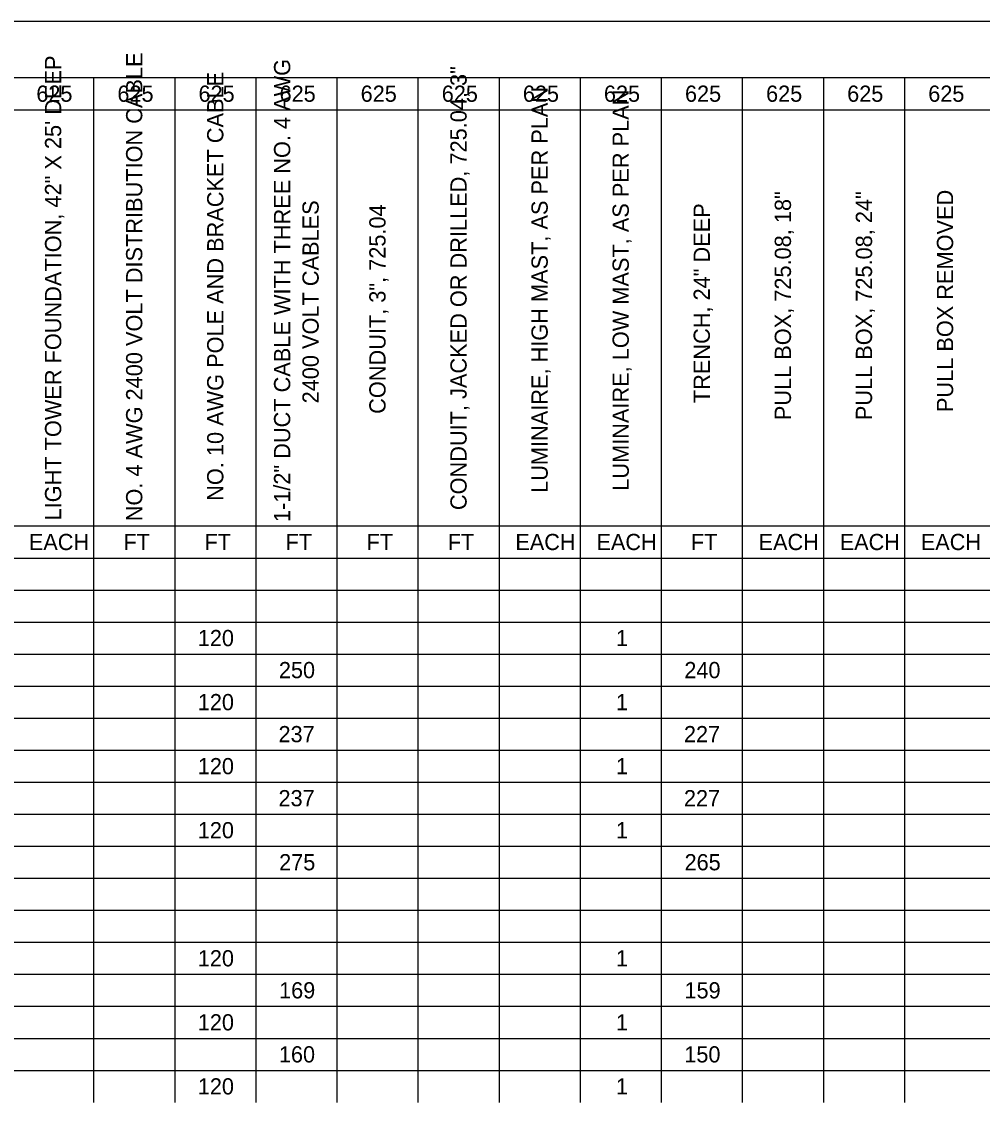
# Model space of a CAD drawing. Extents: x -1022.2 to -988.2, y -965.8 to -943.8.
# Drawn here: x -1005.35 to -996.77, y -953.43 to -943.79 of the extents above; entities that cross this region are included whole.
import ezdxf

# ---------------------------------------------------------------- set-up
doc = ezdxf.new("R2010")
doc.units = 0
for name, color, linetype in [('Default', 7, 'Continuous'), ('SH_Border', 7, 'Continuous'), ('SH_Cut_Line', 7, 'Continuous')]:
    doc.layers.add(name, color=color, linetype=linetype)

msp = doc.modelspace()

# ---------------------------------------------------------------- linework, layer by layer
at = {"layer": 'Default'}
for p, q in [((-1005.4284, -944.2862), (-998.9149, -944.2862)), ((-1004.7047, -944.2862), (-1004.7047, -944.5719)), ((-1003.981, -944.2862), (-1003.981, -944.5719)), ((-1003.2572, -944.2862), (-1003.2572, -944.5719)), ((-1002.5335, -944.2862), (-1002.5335, -944.5719)), ((-1001.8098, -944.2862), (-1001.8098, -944.5719)), ((-1001.0861, -944.2862), (-1001.0861, -944.5719)), ((-1000.3624, -944.2862), (-1000.3624, -944.5719)), ((-999.6387, -944.2862), (-999.6387, -944.5719)), ((-998.9149, -944.2862), (-998.1912, -944.2862)), ((-998.9149, -944.2862), (-998.9149, -944.5719)), ((-998.1912, -944.2862), (-996.0201, -944.2862)), ((-998.1912, -944.2862), (-998.1912, -944.5719)), ((-997.4675, -944.2862), (-997.4675, -944.5719)), ((-1005.4284, -944.5719), (-998.9149, -944.5719)), ((-1004.7047, -944.5719), (-1004.7047, -944.8577)), ((-1003.981, -944.5719), (-1003.981, -944.8577)), ((-1003.2572, -944.5719), (-1003.2572, -944.8577)), ((-1002.5335, -944.5719), (-1002.5335, -944.8577)), ((-1001.8098, -944.5719), (-1001.8098, -944.8577)), ((-1001.0861, -944.5719), (-1001.0861, -944.8577)), ((-1000.3624, -944.5719), (-1000.3624, -944.8577)), ((-999.6387, -944.5719), (-999.6387, -944.8577)), ((-998.9149, -944.5719), (-998.1912, -944.5719)), ((-998.9149, -944.5719), (-998.9149, -944.8577)), ((-998.1912, -944.5719), (-996.0201, -944.5719)), ((-998.1912, -944.5719), (-998.1912, -944.8577)), ((-997.4675, -944.5719), (-997.4675, -944.8577)), ((-1004.7047, -944.8577), (-1004.7047, -945.1434)), ((-1003.981, -944.8577), (-1003.981, -945.1434)), ((-1003.2572, -944.8577), (-1003.2572, -945.1434)), ((-1002.5335, -944.8577), (-1002.5335, -945.1434)), ((-1001.8098, -944.8577), (-1001.8098, -945.1434)), ((-1001.0861, -944.8577), (-1001.0861, -945.1434)), ((-1000.3624, -944.8577), (-1000.3624, -945.1434)), ((-999.6387, -944.8577), (-999.6387, -945.1434)), ((-998.9149, -944.8577), (-998.9149, -945.1434)), ((-998.1912, -944.8577), (-998.1912, -945.1434)), ((-997.4675, -944.8577), (-997.4675, -945.1434)), ((-1004.7047, -945.1434), (-1004.7047, -945.4292)), ((-1003.981, -945.1434), (-1003.981, -945.4292)), ((-1003.2572, -945.1434), (-1003.2572, -945.4292)), ((-1002.5335, -945.1434), (-1002.5335, -945.4292)), ((-1001.8098, -945.1434), (-1001.8098, -945.4292)), ((-1001.0861, -945.1434), (-1001.0861, -945.4292)), ((-1000.3624, -945.1434), (-1000.3624, -945.4292)), ((-999.6387, -945.1434), (-999.6387, -945.4292)), ((-998.9149, -945.1434), (-998.9149, -945.4292)), ((-998.1912, -945.1434), (-998.1912, -945.4292)), ((-997.4675, -945.1434), (-997.4675, -945.4292)), ((-1004.7047, -945.4292), (-1004.7047, -945.7149)), ((-1003.981, -945.4292), (-1003.981, -945.7149)), ((-1003.2572, -945.4292), (-1003.2572, -945.7149)), ((-1002.5335, -945.4292), (-1002.5335, -945.7149)), ((-1001.8098, -945.4292), (-1001.8098, -945.7149)), ((-1001.0861, -945.4292), (-1001.0861, -945.7149)), ((-1000.3624, -945.4292), (-1000.3624, -945.7149)), ((-999.6387, -945.4292), (-999.6387, -945.7149)), ((-998.9149, -945.4292), (-998.9149, -945.7149)), ((-998.1912, -945.4292), (-998.1912, -945.7149)), ((-997.4675, -945.4292), (-997.4675, -945.7149)), ((-1004.7047, -945.7149), (-1004.7047, -946.0006)), ((-1003.981, -945.7149), (-1003.981, -946.0006)), ((-1003.2572, -945.7149), (-1003.2572, -946.0006)), ((-1002.5335, -945.7149), (-1002.5335, -946.0006)), ((-1001.8098, -945.7149), (-1001.8098, -946.0006)), ((-1001.0861, -945.7149), (-1001.0861, -946.0006)), ((-1000.3624, -945.7149), (-1000.3624, -946.0006)), ((-999.6387, -945.7149), (-999.6387, -946.0006)), ((-998.9149, -945.7149), (-998.9149, -946.0006)), ((-998.1912, -945.7149), (-998.1912, -946.0006)), ((-997.4675, -945.7149), (-997.4675, -946.0006)), ((-1004.7047, -946.0006), (-1004.7047, -946.2864)), ((-1003.981, -946.0006), (-1003.981, -946.2864)), ((-1003.2572, -946.0006), (-1003.2572, -946.2864)), ((-1002.5335, -946.0006), (-1002.5335, -946.2864)), ((-1001.8098, -946.0006), (-1001.8098, -946.2864)), ((-1001.0861, -946.0006), (-1001.0861, -946.2864)), ((-1000.3624, -946.0006), (-1000.3624, -946.2864)), ((-999.6387, -946.0006), (-999.6387, -946.2864)), ((-998.9149, -946.0006), (-998.9149, -946.2864)), ((-998.1912, -946.0006), (-998.1912, -946.2864)), ((-997.4675, -946.0006), (-997.4675, -946.2864)), ((-1004.7047, -946.2864), (-1004.7047, -946.8578)), ((-1003.981, -946.2864), (-1003.981, -946.8578)), ((-1003.2572, -946.2864), (-1003.2572, -946.8578)), ((-1002.5335, -946.2864), (-1002.5335, -946.8578)), ((-1001.8098, -946.2864), (-1001.8098, -946.8578)), ((-1001.0861, -946.2864), (-1001.0861, -946.8578)), ((-1000.3624, -946.2864), (-1000.3624, -946.8578)), ((-999.6387, -946.2864), (-999.6387, -946.8578)), ((-998.9149, -946.2864), (-998.9149, -946.8578)), ((-998.1912, -946.2864), (-998.1912, -946.8578)), ((-997.4675, -946.2864), (-997.4675, -946.8578)), ((-1004.7047, -946.8578), (-1004.7047, -947.7151)), ((-1003.981, -946.8578), (-1003.981, -947.7151)), ((-1003.2572, -946.8578), (-1003.2572, -947.7151)), ((-1002.5335, -946.8578), (-1002.5335, -947.7151)), ((-1001.8098, -946.8578), (-1001.8098, -947.7151)), ((-1001.0861, -946.8578), (-1001.0861, -947.7151)), ((-1000.3624, -946.8578), (-1000.3624, -947.7151)), ((-999.6387, -946.8578), (-999.6387, -947.7151)), ((-998.9149, -946.8578), (-998.9149, -947.7151)), ((-998.1912, -946.8578), (-998.1912, -947.7151)), ((-997.4675, -946.8578), (-997.4675, -947.7151)), ((-1004.7047, -947.7151), (-1004.7047, -948.0008)), ((-1003.981, -947.7151), (-1003.981, -948.0008)), ((-1003.2572, -947.7151), (-1003.2572, -948.0008)), ((-1002.5335, -947.7151), (-1002.5335, -948.0008)), ((-1001.8098, -947.7151), (-1001.8098, -948.0008)), ((-1001.0861, -947.7151), (-1001.0861, -948.0008)), ((-1000.3624, -947.7151), (-1000.3624, -948.0008)), ((-999.6387, -947.7151), (-999.6387, -948.0008)), ((-998.9149, -947.7151), (-998.9149, -948.0008)), ((-998.1912, -947.7151), (-998.1912, -948.0008)), ((-997.4675, -947.7151), (-997.4675, -948.0008)), ((-1004.7047, -948.0008), (-1004.7047, -948.5723)), ((-1003.981, -948.0008), (-1003.981, -948.5723)), ((-1003.2572, -948.0008), (-1003.2572, -948.5723)), ((-1002.5335, -948.0008), (-1002.5335, -948.5723)), ((-1001.8098, -948.0008), (-1001.8098, -948.5723)), ((-1001.0861, -948.0008), (-1001.0861, -948.5723)), ((-1000.3624, -948.0008), (-1000.3624, -948.5723)), ((-999.6387, -948.0008), (-999.6387, -948.5723)), ((-998.9149, -948.0008), (-998.9149, -948.5723)), ((-998.1912, -948.0008), (-998.1912, -948.5723)), ((-997.4675, -948.0008), (-997.4675, -948.5723)), ((-1005.4284, -948.2865), (-998.9149, -948.2865)), ((-998.9149, -948.2865), (-998.1912, -948.2865)), ((-998.1912, -948.2865), (-996.0201, -948.2865)), ((-1005.4284, -948.5723), (-998.9149, -948.5723)), ((-1004.7047, -948.5723), (-1004.7047, -948.858)), ((-1003.981, -948.5723), (-1003.981, -948.858)), ((-1003.2572, -948.5723), (-1003.2572, -948.858)), ((-1002.5335, -948.5723), (-1002.5335, -948.858)), ((-1001.8098, -948.5723), (-1001.8098, -948.858)), ((-1001.0861, -948.5723), (-1001.0861, -948.858)), ((-1000.3624, -948.5723), (-1000.3624, -948.858)), ((-999.6387, -948.5723), (-999.6387, -948.858)), ((-998.9149, -948.5723), (-998.1912, -948.5723)), ((-998.9149, -948.5723), (-998.9149, -948.858)), ((-998.1912, -948.5723), (-996.0201, -948.5723)), ((-998.1912, -948.5723), (-998.1912, -948.858)), ((-997.4675, -948.5723), (-997.4675, -948.858)), ((-1005.4284, -948.858), (-998.9149, -948.858)), ((-1004.7047, -948.858), (-1004.7047, -950.001)), ((-1003.981, -948.858), (-1003.981, -950.001)), ((-1003.2572, -948.858), (-1003.2572, -950.001)), ((-1002.5335, -948.858), (-1002.5335, -950.001)), ((-1001.8098, -948.858), (-1001.8098, -950.001)), ((-1001.0861, -948.858), (-1001.0861, -950.001)), ((-1000.3624, -948.858), (-1000.3624, -950.001)), ((-999.6387, -948.858), (-999.6387, -950.001)), ((-998.9149, -948.858), (-998.1912, -948.858)), ((-998.9149, -948.858), (-998.9149, -950.001)), ((-998.1912, -948.858), (-996.0201, -948.858)), ((-998.1912, -948.858), (-998.1912, -950.001)), ((-997.4675, -948.858), (-997.4675, -950.001)), ((-1005.4284, -949.1437), (-998.9149, -949.1437)), ((-998.9149, -949.1437), (-998.1912, -949.1437)), ((-998.1912, -949.1437), (-996.0201, -949.1437)), ((-1005.4284, -949.4295), (-998.9149, -949.4295)), ((-998.9149, -949.4295), (-998.1912, -949.4295)), ((-998.1912, -949.4295), (-996.0201, -949.4295)), ((-1005.4284, -949.7152), (-998.9149, -949.7152)), ((-998.9149, -949.7152), (-998.1912, -949.7152)), ((-998.1912, -949.7152), (-996.0201, -949.7152)), ((-1005.4284, -950.001), (-998.9149, -950.001)), ((-1004.7047, -950.001), (-1004.7047, -950.2867)), ((-1003.981, -950.001), (-1003.981, -950.2867)), ((-1003.2572, -950.001), (-1003.2572, -950.2867)), ((-1002.5335, -950.001), (-1002.5335, -950.2867)), ((-1001.8098, -950.001), (-1001.8098, -950.2867)), ((-1001.0861, -950.001), (-1001.0861, -950.2867)), ((-1000.3624, -950.001), (-1000.3624, -950.2867)), ((-999.6387, -950.001), (-999.6387, -950.2867)), ((-998.9149, -950.001), (-998.1912, -950.001)), ((-998.9149, -950.001), (-998.9149, -950.2867)), ((-998.1912, -950.001), (-996.0201, -950.001)), ((-998.1912, -950.001), (-998.1912, -950.2867)), ((-997.4675, -950.001), (-997.4675, -950.2867)), ((-1005.4284, -950.2867), (-998.9149, -950.2867)), ((-1004.7047, -950.2867), (-1004.7047, -950.8582)), ((-1003.981, -950.2867), (-1003.981, -950.8582)), ((-1003.2572, -950.2867), (-1003.2572, -950.8582)), ((-1002.5335, -950.2867), (-1002.5335, -950.8582)), ((-1001.8098, -950.2867), (-1001.8098, -950.8582)), ((-1001.0861, -950.2867), (-1001.0861, -950.8582)), ((-1000.3624, -950.2867), (-1000.3624, -950.8582)), ((-999.6387, -950.2867), (-999.6387, -950.8582)), ((-998.9149, -950.2867), (-998.1912, -950.2867)), ((-998.9149, -950.2867), (-998.9149, -950.8582)), ((-998.1912, -950.2867), (-996.0201, -950.2867)), ((-998.1912, -950.2867), (-998.1912, -950.8582)), ((-997.4675, -950.2867), (-997.4675, -950.8582)), ((-1005.4284, -950.5724), (-998.9149, -950.5724)), ((-998.9149, -950.5724), (-998.1912, -950.5724)), ((-998.1912, -950.5724), (-996.0201, -950.5724)), ((-1005.4284, -950.8582), (-998.9149, -950.8582)), ((-1004.7047, -950.8582), (-1004.7047, -951.4296)), ((-1003.981, -950.8582), (-1003.981, -951.4296)), ((-1003.2572, -950.8582), (-1003.2572, -951.4296)), ((-1002.5335, -950.8582), (-1002.5335, -951.4296)), ((-1001.8098, -950.8582), (-1001.8098, -951.4296)), ((-1001.0861, -950.8582), (-1001.0861, -951.4296)), ((-1000.3624, -950.8582), (-1000.3624, -951.4296)), ((-999.6387, -950.8582), (-999.6387, -951.4296)), ((-998.9149, -950.8582), (-998.1912, -950.8582)), ((-998.9149, -950.8582), (-998.9149, -951.4296)), ((-998.1912, -950.8582), (-996.0201, -950.8582)), ((-998.1912, -950.8582), (-998.1912, -951.4296)), ((-997.4675, -950.8582), (-997.4675, -951.4296)), ((-1005.4284, -951.1439), (-998.9149, -951.1439)), ((-998.9149, -951.1439), (-998.1912, -951.1439)), ((-998.1912, -951.1439), (-996.0201, -951.1439)), ((-1005.4284, -951.4296), (-998.9149, -951.4296)), ((-1004.7047, -951.4296), (-1004.7047, -951.7154)), ((-1003.981, -951.4296), (-1003.981, -951.7154)), ((-1003.2572, -951.4296), (-1003.2572, -951.7154)), ((-1002.5335, -951.4296), (-1002.5335, -951.7154)), ((-1001.8098, -951.4296), (-1001.8098, -951.7154)), ((-1001.0861, -951.4296), (-1001.0861, -951.7154)), ((-1000.3624, -951.4296), (-1000.3624, -951.7154)), ((-999.6387, -951.4296), (-999.6387, -951.7154)), ((-998.9149, -951.4296), (-998.1912, -951.4296)), ((-998.9149, -951.4296), (-998.9149, -951.7154)), ((-998.1912, -951.4296), (-996.0201, -951.4296)), ((-998.1912, -951.4296), (-998.1912, -951.7154)), ((-997.4675, -951.4296), (-997.4675, -951.7154)), ((-1005.4284, -951.7154), (-998.9149, -951.7154)), ((-1004.7047, -951.7154), (-1004.7047, -952.2869)), ((-1003.981, -951.7154), (-1003.981, -952.2869)), ((-1003.2572, -951.7154), (-1003.2572, -952.2869)), ((-1002.5335, -951.7154), (-1002.5335, -952.2869)), ((-1001.8098, -951.7154), (-1001.8098, -952.2869)), ((-1001.0861, -951.7154), (-1001.0861, -952.2869)), ((-1000.3624, -951.7154), (-1000.3624, -952.2869)), ((-999.6387, -951.7154), (-999.6387, -952.2869)), ((-998.9149, -951.7154), (-998.1912, -951.7154)), ((-998.9149, -951.7154), (-998.9149, -952.2869)), ((-998.1912, -951.7154), (-996.0201, -951.7154)), ((-998.1912, -951.7154), (-998.1912, -952.2869)), ((-997.4675, -951.7154), (-997.4675, -952.2869)), ((-1005.4284, -952.0011), (-998.9149, -952.0011)), ((-998.9149, -952.0011), (-998.1912, -952.0011)), ((-998.1912, -952.0011), (-996.0201, -952.0011)), ((-1005.4284, -952.2869), (-998.9149, -952.2869)), ((-1004.7047, -952.2869), (-1004.7047, -952.5726)), ((-1003.981, -952.2869), (-1003.981, -952.5726)), ((-1003.2572, -952.2869), (-1003.2572, -952.5726)), ((-1002.5335, -952.2869), (-1002.5335, -952.5726)), ((-1001.8098, -952.2869), (-1001.8098, -952.5726)), ((-1001.0861, -952.2869), (-1001.0861, -952.5726)), ((-1000.3624, -952.2869), (-1000.3624, -952.5726)), ((-999.6387, -952.2869), (-999.6387, -952.5726)), ((-998.9149, -952.2869), (-998.1912, -952.2869)), ((-998.9149, -952.2869), (-998.9149, -952.5726)), ((-998.1912, -952.2869), (-996.0201, -952.2869)), ((-998.1912, -952.2869), (-998.1912, -952.5726)), ((-997.4675, -952.2869), (-997.4675, -952.5726)), ((-1005.4284, -952.5726), (-998.9149, -952.5726)), ((-1004.7047, -952.5726), (-1004.7047, -953.4298)), ((-1003.981, -952.5726), (-1003.981, -953.4298)), ((-1003.2572, -952.5726), (-1003.2572, -953.4298)), ((-1002.5335, -952.5726), (-1002.5335, -953.4298)), ((-1001.8098, -952.5726), (-1001.8098, -953.4298)), ((-1001.0861, -952.5726), (-1001.0861, -953.4298)), ((-1000.3624, -952.5726), (-1000.3624, -953.4298)), ((-999.6387, -952.5726), (-999.6387, -953.4298)), ((-998.9149, -952.5726), (-998.1912, -952.5726)), ((-998.9149, -952.5726), (-998.9149, -953.4298)), ((-998.1912, -952.5726), (-996.0201, -952.5726)), ((-998.1912, -952.5726), (-998.1912, -953.4298)), ((-997.4675, -952.5726), (-997.4675, -953.4298)), ((-1005.4284, -952.8583), (-998.9149, -952.8583)), ((-998.9149, -952.8583), (-998.1912, -952.8583)), ((-998.1912, -952.8583), (-996.0201, -952.8583)), ((-1005.4284, -953.1441), (-998.9149, -953.1441)), ((-998.9149, -953.1441), (-998.1912, -953.1441)), ((-998.1912, -953.1441), (-996.0201, -953.1441))]:
    msp.add_line(p, q, dxfattribs=at)
at = {"layer": 'SH_Border'}
msp.add_lwpolyline([(-1020.7494, -944.2862), (-988.7494, -944.2862), (-988.7494, -965.2862), (-1020.7494, -965.2862)], close=True, dxfattribs=at)
at = {"layer": 'SH_Cut_Line'}
msp.add_lwpolyline([(-1022.2494, -965.7862), (-988.2494, -965.7862), (-988.2494, -943.7862), (-1022.2494, -943.7862)], close=True, dxfattribs=at)

# ---------------------------------------------------------------- texts
at = {"layer": 'Default'}
for s, p in [('LIGHT TOWER FOUNDATION, 42" X 25\' DEEP', (-1004.994, -948.2371)), ('NO. 4 AWG 2400 VOLT DISTRIBUTION CABLE', (-1004.2703, -948.2446)), ('1-1/2" DUCT CABLE WITH THREE NO. 4 AWG ', (-1002.9498, -948.2523)), ('CONDUIT, JACKED OR DRILLED, 725.04, 3"', (-1001.3754, -948.1448)), ('NO. 10 AWG POLE AND BRACKET CABLE', (-1003.5466, -948.062)), ('LUMINAIRE, HIGH MAST, AS PER PLAN', (-1000.6517, -947.9914)), ('LUMINAIRE, LOW MAST, AS PER PLAN', (-999.928, -947.972)), ('PULL BOX, 725.08, 18"', (-998.4805, -947.3423)), ('PULL BOX, 725.08, 24"', (-997.7568, -947.3423)), ('PULL BOX REMOVED', (-997.0331, -947.2702)), ('2400 VOLT CABLES', (-1002.6959, -947.1929)), ('CONDUIT, 3", 725.04', (-1002.0991, -947.2861)), ('TRENCH, 24" DEEP', (-999.2043, -947.1904))]:
    msp.add_text(s, height=0.145085, rotation=90, dxfattribs=at).set_placement(p)
for s, height, p in [('625', 0.14457, (-1005.2161, -944.5014)), ('625', 0.14457, (-1004.4924, -944.5014)), ('625', 0.14457, (-1003.7687, -944.5014)), ('625', 0.14457, (-1003.045, -944.5014)), ('625', 0.14457, (-1002.3213, -944.5014)), ('625', 0.14457, (-1001.5975, -944.5014)), ('625', 0.14457, (-1000.8738, -944.5014)), ('625', 0.14457, (-1000.1501, -944.5014)), ('625', 0.14457, (-999.4264, -944.5014)), ('625', 0.14457, (-998.7027, -944.5014)), ('625', 0.14457, (-997.9789, -944.5014)), ('625', 0.14457, (-997.2552, -944.5014)), ('EACH', 0.14457, (-1005.2826, -948.5017)), ('EACH', 0.14457, (-1000.9403, -948.5017)), ('EACH', 0.14457, (-1000.2166, -948.5017)), ('EACH', 0.14457, (-998.7691, -948.5017)), ('EACH', 0.14457, (-998.0454, -948.5017)), ('EACH', 0.14457, (-997.3217, -948.5017)), ('FT', 0.14457, (-1004.4391, -948.5017)), ('FT', 0.14457, (-1003.7154, -948.5017)), ('FT', 0.14457, (-1002.9916, -948.5017)), ('FT', 0.14457, (-1002.2679, -948.5017)), ('FT', 0.14457, (-1001.5442, -948.5017)), ('FT', 0.14457, (-999.373, -948.5017)), ('120', 0.14457, (-1003.7748, -949.3589)), ('1', 0.1446, (-1000.0425, -949.3589)), ('250', 0.14457, (-1003.0511, -949.6446)), ('240', 0.14457, (-999.4325, -949.6446)), ('120', 0.14457, (-1003.7748, -949.9304)), ('1', 0.1446, (-1000.0425, -949.9304)), ('237', 0.14457, (-1003.0545, -950.2161)), ('227', 0.14457, (-999.4359, -950.2161)), ('120', 0.14457, (-1003.7748, -950.5018)), ('1', 0.1446, (-1000.0425, -950.5018)), ('237', 0.14457, (-1003.0545, -950.7876)), ('227', 0.14457, (-999.4359, -950.7876)), ('120', 0.14457, (-1003.7748, -951.0733)), ('1', 0.1446, (-1000.0425, -951.0733)), ('275', 0.14457, (-1003.0488, -951.3591)), ('265', 0.14457, (-999.4302, -951.3591)), ('120', 0.14457, (-1003.7748, -952.2163)), ('1', 0.1446, (-1000.0425, -952.2163)), ('169', 0.14457, (-1003.0494, -952.502)), ('159', 0.14457, (-999.4309, -952.502)), ('120', 0.14457, (-1003.7748, -952.7877)), ('1', 0.1446, (-1000.0425, -952.7877)), ('160', 0.14457, (-1003.0511, -953.0735)), ('150', 0.14457, (-999.4325, -953.0735)), ('120', 0.14457, (-1003.7748, -953.3592)), ('1', 0.1446, (-1000.0425, -953.3592))]:
    msp.add_text(s, height=height, dxfattribs=at).set_placement(p)

doc.saveas('drawing.dxf')
